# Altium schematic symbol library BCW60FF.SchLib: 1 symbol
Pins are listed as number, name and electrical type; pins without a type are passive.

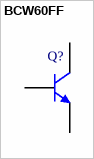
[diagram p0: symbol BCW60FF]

## BCW60FF
designator Q?
NPN Silicon AF Transistor, 32 V VCEO, 100 mA IC, SOT23, Reel, Green; Manufacturer: Infineon; PartNumber: BCW60FF; F (typ): 1 dB; fT (typ): 250 MHz; Green: TRUE; IC: 2 mA; IC (max): 100 mA; ICBO (max): 20 nA; ICM (max): 200 mA; VCBO (max): 32 V; VCE: 5 V; VEBO (max): 6 V
footprint INF-SOT23_N (SOT23, 3-Leads, Body 2.9x1.3 mm, Pitch 0.95 mm, IPC Medium Density)
footprint INF-SOT23_L (SOT23, 3-Leads, Body 2.9x1.3 mm, Pitch 0.95 mm, IPC High Density)
footprint INF-SOT23_M (SOT23, 3-Leads, Body 2.9x1.3 mm, Pitch 0.95 mm, IPC Low Density)
pins: 1 B, 2 E, 3 C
